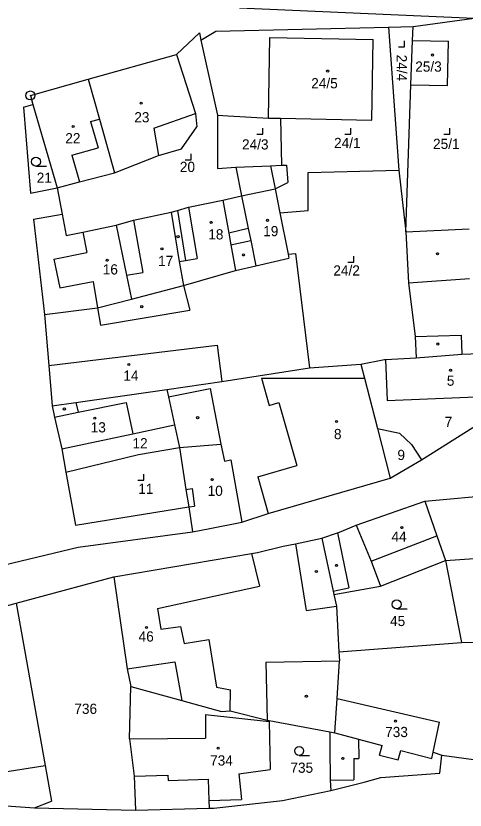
# Model space of a CAD drawing. Extents: x -779596 to -776743, y -1030330 to -1024513.
# Drawn here: x -778013.4 to -777938.4, y -1024989.8 to -1024857.5 of the extents above; entities that cross this region are included whole.
import ezdxf

# ---------------------------------------------------------------- set-up
doc = ezdxf.new("R2010")
doc.units = 0
for name, color, linetype in [('hranice parcel', 7, 'Continuous'), ('hranice vnitřní', 7, 'Continuous'), ('kultura', 7, 'Continuous'), ('Kód', 7, 'Continuous'), ('č_pacel stav_', 7, 'Continuous'), ('č_parcel poz_', 7, 'Continuous')]:
    doc.layers.add(name, color=color, linetype=linetype)

msp = doc.modelspace()

# ---------------------------------------------------------------- linework, layer by layer
at = {"layer": 'hranice parcel'}
for points in [[(-777976.03, -1024856.17), (-777936.91, -1024857.84)], [(-777947.1, -1024859.26), (-777936.91, -1024857.84)], [(-777986.58, -1024863.92), (-777982.75, -1024860.33)], [(-777982.75, -1024860.33), (-777982.49, -1024861.51)], [(-777982.49, -1024861.51), (-777979.99, -1024860.03)], [(-777979.99, -1024860.03), (-777951.2, -1024859.36)], [(-777951.2, -1024859.36), (-777947.1, -1024859.26)], [(-777951.2, -1024859.36), (-777949.5, -1024883.2)], [(-777947.18, -1024861.56), (-777947.1, -1024859.26)], [(-777982.49, -1024861.51), (-777979.73, -1024874.05)], [(-777971.23, -1024874.51), (-777970.97, -1024861.09)], [(-777970.97, -1024861.09), (-777953.73, -1024861.43)], [(-777953.99, -1024874.84), (-777953.73, -1024861.43)], [(-777947.45, -1024868.95), (-777947.18, -1024861.56)], [(-777947.18, -1024861.56), (-777941.2, -1024861.68)], [(-777941.34, -1024869.07), (-777941.2, -1024861.68)], [(-778001.29, -1024868.05), (-777986.58, -1024863.92)], [(-777986.58, -1024863.92), (-777983.39, -1024873.77)], [(-778010.93, -1024870.75), (-778001.29, -1024868.05)], [(-778001.29, -1024868.05), (-777999.41, -1024874.7)], [(-777948.32, -1024893.45), (-777947.45, -1024868.95)], [(-777947.45, -1024868.95), (-777941.34, -1024869.07)], [(-778010.93, -1024870.75), (-778010.5, -1024872.23)], [(-778012.1, -1024872.68), (-778010.5, -1024872.23)], [(-778010.5, -1024872.23), (-778006.46, -1024886.12)], [(-778012.1, -1024872.68), (-778010.91, -1024887.01)], [(-777999.41, -1024874.7), (-777996.89, -1024883.62)], [(-777983.39, -1024873.77), (-777983.17, -1024875.96)], [(-777979.73, -1024874.05), (-777977.93, -1024874.15)], [(-777979.73, -1024874.05), (-777979.72, -1024882.89)], [(-777977.93, -1024874.15), (-777971.23, -1024874.51)], [(-777971.23, -1024874.51), (-777969.23, -1024874.55)], [(-777969.23, -1024874.55), (-777969.04, -1024882.38)], [(-777969.23, -1024874.55), (-777953.99, -1024874.84)], [(-777985.73, -1024879.66), (-777983.17, -1024875.96)], [(-777989.57, -1024880.74), (-777985.73, -1024879.66)], [(-777996.89, -1024883.62), (-777989.57, -1024880.74)], [(-777979.72, -1024882.89), (-777976.68, -1024882.72)], [(-777976.68, -1024882.72), (-777970.86, -1024882.46)], [(-777976.68, -1024882.72), (-777975.72, -1024887.47)], [(-777970.86, -1024882.46), (-777969.04, -1024882.38)], [(-777969.04, -1024882.38), (-777968.24, -1024882.35)], [(-777968.24, -1024882.35), (-777968, -1024885.23)], [(-778002.75, -1024885.15), (-777996.89, -1024883.62)], [(-777964.6, -1024883.6), (-777949.5, -1024883.2)], [(-777964.6, -1024889.9), (-777964.6, -1024883.6)], [(-777949.5, -1024883.2), (-777948.32, -1024893.45)], [(-778006.46, -1024886.12), (-778002.75, -1024885.15)], [(-777970.1, -1024886.29), (-777968, -1024885.23)], [(-778010.91, -1024887.01), (-778006.46, -1024886.12)], [(-778006.46, -1024886.12), (-778005.64, -1024890.52)], [(-777970.1, -1024886.29), (-777969.3, -1024890.31)], [(-777984.56, -1024889.36), (-777978.84, -1024888.2)], [(-777978.84, -1024888.2), (-777975.72, -1024887.47)], [(-777978.84, -1024888.2), (-777977.83, -1024893.69)], [(-777986.4, -1024889.89), (-777984.56, -1024889.36)], [(-778010.4, -1024891.35), (-778005.64, -1024890.52)], [(-778005.64, -1024890.52), (-778004.97, -1024894.1)], [(-777993.71, -1024891.52), (-777987.44, -1024890.17)], [(-777987.44, -1024890.17), (-777986.4, -1024889.89)], [(-777987.44, -1024890.17), (-777986.13, -1024898.41)], [(-777969.3, -1024890.31), (-777964.6, -1024889.9)], [(-777969.3, -1024890.31), (-777967.93, -1024897.19)], [(-778010.4, -1024891.35), (-778008.58, -1024907.27)], [(-777996.65, -1024892.36), (-777993.71, -1024891.52)], [(-778004.97, -1024894.1), (-778002.18, -1024893.52)], [(-778002.18, -1024893.52), (-777996.65, -1024892.36)], [(-777996.65, -1024892.36), (-777994.91, -1024900.71)], [(-777948.32, -1024893.45), (-777937.75, -1024892.96)], [(-777948.32, -1024893.45), (-777947.88, -1024901.99)], [(-777977.83, -1024893.69), (-777977.48, -1024895.62)], [(-777977.48, -1024895.62), (-777976.7, -1024899.92)], [(-777967.93, -1024897.19), (-777966.73, -1024897.09)], [(-777967.93, -1024897.19), (-777967.8, -1024897.86)], [(-777966.73, -1024897.09), (-777964.35, -1024916.13)], [(-777986.13, -1024898.41), (-777985.4, -1024902.41)], [(-777973.3, -1024899.13), (-777967.8, -1024897.86)], [(-777985.4, -1024902.41), (-777976.7, -1024899.92)], [(-777976.7, -1024899.92), (-777973.3, -1024899.13)], [(-777994.91, -1024900.71), (-777994.08, -1024904.67)], [(-777994.08, -1024904.67), (-777985.4, -1024902.41)], [(-777947.88, -1024901.99), (-777946.73, -1024910.93)], [(-777999.74, -1024906.13), (-777994.08, -1024904.67)], [(-778008.58, -1024907.27), (-777999.74, -1024906.13)], [(-778008.58, -1024907.27), (-778007.87, -1024915.76)], [(-777946.73, -1024910.93), (-777946.58, -1024914.45)], [(-777951.86, -1024914.77), (-777951.7, -1024914.76)], [(-777951.7, -1024914.76), (-777946.58, -1024914.45)], [(-777951.7, -1024914.76), (-777951.42, -1024921.59)], [(-778007.87, -1024915.76), (-778007.31, -1024922.47)], [(-777964.35, -1024916.13), (-777955.82, -1024915.54)], [(-777955.82, -1024915.54), (-777951.86, -1024914.77)], [(-777955.82, -1024915.54), (-777955.22, -1024917.86)], [(-777979, -1024918.44), (-777964.35, -1024916.13)], [(-777988.18, -1024919.75), (-777979, -1024918.44)], [(-777955.22, -1024917.86), (-777953.06, -1024926.27)], [(-778003.35, -1024921.91), (-777988.18, -1024919.75)], [(-777988.18, -1024919.75), (-777987.91, -1024920.97)], [(-777987.91, -1024920.97), (-777986.89, -1024925.66)], [(-777951.42, -1024921.59), (-777931.23, -1024920.76)], [(-777945.67, -1024931.45), (-777928.59, -1024920.69)], [(-778007.31, -1024922.47), (-778003.35, -1024921.91)], [(-778007.31, -1024922.47), (-778006.88, -1024924.34)], [(-778006.88, -1024924.34), (-778005.69, -1024929.61)], [(-777993.83, -1024927.12), (-777986.89, -1024925.66)], [(-777986.89, -1024925.66), (-777986.08, -1024929.41)], [(-777953.06, -1024926.27), (-777950.94, -1024934.52)], [(-777953.06, -1024926.27), (-777949.39, -1024927.01)], [(-778005.69, -1024929.61), (-777993.83, -1024927.12)], [(-777949.39, -1024927.01), (-777947.35, -1024928.93)], [(-777986.08, -1024929.41), (-777979.14, -1024928.83)], [(-777979.14, -1024928.83), (-777978.58, -1024931.69)], [(-777947.35, -1024928.93), (-777945.67, -1024931.45)], [(-778005.69, -1024929.61), (-778005.03, -1024933.5)], [(-778005.03, -1024933.5), (-777992.92, -1024930.56)], [(-777992.92, -1024930.56), (-777986.08, -1024929.41)], [(-777986.08, -1024929.41), (-777984.99, -1024936.41)], [(-777978.58, -1024931.69), (-777977.51, -1024931.49)], [(-777977.51, -1024931.49), (-777975.66, -1024941.84)], [(-777950.94, -1024934.52), (-777945.67, -1024931.45)], [(-778005.03, -1024933.5), (-778003.43, -1024942.34)], [(-777971.26, -1024940.42), (-777950.94, -1024934.52)], [(-777984.99, -1024936.41), (-777984.53, -1024939.32)], [(-777945.13, -1024938.37), (-777932.96, -1024937.24)], [(-777956.59, -1024942.37), (-777945.13, -1024938.37)], [(-777945.13, -1024938.37), (-777943.13, -1024944.14)], [(-778003.43, -1024942.34), (-777984.53, -1024939.32)], [(-777984.53, -1024939.32), (-777983.88, -1024943.49)], [(-777975.66, -1024941.84), (-777971.26, -1024940.42)], [(-777980.98, -1024942.91), (-777975.66, -1024941.84)], [(-777959.36, -1024943.52), (-777956.59, -1024942.37)], [(-778002.98, -1024946.02), (-777983.88, -1024943.49)], [(-777983.88, -1024943.49), (-777980.98, -1024942.91)], [(-777962.34, -1024944.54), (-777959.68, -1024943.63)], [(-777959.68, -1024943.63), (-777959.36, -1024943.52)], [(-777966.7, -1024945.44), (-777962.34, -1024944.54)], [(-777962.34, -1024944.54), (-777960.42, -1024953.35)], [(-777943.13, -1024944.14), (-777941.71, -1024948.25)], [(-778018.06, -1024949.63), (-778002.98, -1024946.02)], [(-777973.07, -1024946.92), (-777968.75, -1024945.87)], [(-777968.75, -1024945.87), (-777966.7, -1024945.44)], [(-777997.02, -1024950.99), (-777974.06, -1024947.09)], [(-777974.06, -1024947.09), (-777973.07, -1024946.92)], [(-777952.52, -1024952.51), (-777941.71, -1024948.25)], [(-777941.71, -1024948.25), (-777939.01, -1024961.93)], [(-778013.31, -1024955.35), (-777997.02, -1024950.99)], [(-777997.02, -1024950.99), (-777994.8, -1024966.29)], [(-777960.3, -1024953.91), (-777952.52, -1024952.51)], [(-777960.42, -1024953.35), (-777960.3, -1024953.91)], [(-777960.3, -1024953.91), (-777959.88, -1024955.86)], [(-778022.98, -1024958.03), (-778013.31, -1024955.35)], [(-778013.31, -1024955.35), (-778008.47, -1024982.41)], [(-777959.88, -1024955.86), (-777959.47, -1024963.47)], [(-777959.47, -1024963.47), (-777939.01, -1024961.93)], [(-777939.01, -1024961.93), (-777928.89, -1024961.65)], [(-777959.47, -1024963.47), (-777959.37, -1024964.95)], [(-777959.77, -1024971.24), (-777959.37, -1024964.95)], [(-777994.8, -1024966.29), (-777994.17, -1024969.23)], [(-777994.39, -1024977.98), (-777994.17, -1024969.23)], [(-777994.17, -1024969.23), (-777985.66, -1024971.57)], [(-777985.66, -1024971.57), (-777979.03, -1024973.38)], [(-777960.14, -1024976.97), (-777959.77, -1024971.24)], [(-777959.77, -1024971.24), (-777942.72, -1024975.21)], [(-777979.03, -1024973.38), (-777977.59, -1024973.27)], [(-777977.59, -1024973.27), (-777971.41, -1024974.83)], [(-777971.41, -1024974.83), (-777971.11, -1024974.89)], [(-777971.11, -1024974.89), (-777961, -1024976.81)], [(-777971.11, -1024974.89), (-777971.1, -1024975.08)], [(-777971.1, -1024975.08), (-777970.91, -1024983.06)], [(-777943.75, -1024980.21), (-777942.72, -1024975.21)], [(-777961, -1024976.81), (-777960.98, -1024979.41)], [(-777961, -1024976.81), (-777960.14, -1024976.97)], [(-777994.39, -1024977.98), (-777993.62, -1024984.18)], [(-777960.98, -1024979.41), (-777960.93, -1024984.85)], [(-777943.75, -1024980.21), (-777942.33, -1024980.67)], [(-777942.63, -1024983.67), (-777942.33, -1024980.67)], [(-777942.33, -1024980.67), (-777925.63, -1024982.94)], [(-778008.47, -1024982.41), (-778007.41, -1024988.34)], [(-777976.18, -1024983.81), (-777970.91, -1024983.06)], [(-777993.62, -1024984.18), (-777993.41, -1024989.84)], [(-777976.18, -1024983.81), (-777975.73, -1024988.07)], [(-777960.93, -1024984.85), (-777960.81, -1024986.57)], [(-777955.25, -1024985.21), (-777952.48, -1024984.43)], [(-777952.48, -1024984.43), (-777942.63, -1024983.67)], [(-777960.81, -1024986.57), (-777955.25, -1024985.21)], [(-777968.89, -1024988.24), (-777960.81, -1024986.57)], [(-778027.49, -1024988.25), (-778010.26, -1024989.46)], [(-778010.26, -1024989.46), (-778007.41, -1024988.34)], [(-777981.17, -1024988.26), (-777975.73, -1024988.07)], [(-777981.17, -1024988.26), (-777981.12, -1024989.53)], [(-777980.35, -1024989.51), (-777968.89, -1024988.24)], [(-778010.26, -1024989.46), (-777993.41, -1024989.84)], [(-777993.41, -1024989.84), (-777981.12, -1024989.53)], [(-777981.12, -1024989.53), (-777980.35, -1024989.51)]]:
    msp.add_lwpolyline(points, dxfattribs=at)
at = {"layer": 'hranice vnitřní'}
for points in [[(-778000.91, -1024875.11), (-777999.41, -1024874.7)], [(-777990.33, -1024876.18), (-777983.39, -1024873.77)], [(-778000.91, -1024875.11), (-777999.65, -1024879.46)], [(-777990.33, -1024876.18), (-777989.57, -1024880.74)], [(-778004.04, -1024880.72), (-777999.65, -1024879.46)], [(-778004.04, -1024880.72), (-778002.75, -1024885.15)], [(-777970.86, -1024882.46), (-777970.1, -1024886.29)], [(-777975.72, -1024887.47), (-777970.1, -1024886.29)], [(-777975.72, -1024887.47), (-777974.59, -1024892.92)], [(-777984.56, -1024889.36), (-777983.09, -1024897.93)], [(-777986.4, -1024889.89), (-777985.07, -1024898.24)], [(-777993.71, -1024891.52), (-777992.18, -1024900.23)], [(-778002.18, -1024893.52), (-778001.51, -1024896.92)], [(-777974.59, -1024892.92), (-777977.83, -1024893.69)], [(-777974.59, -1024892.92), (-777974.17, -1024894.93)], [(-777977.48, -1024895.62), (-777974.17, -1024894.93)], [(-777974.17, -1024894.93), (-777973.3, -1024899.13)], [(-778007, -1024898), (-778001.51, -1024896.92)], [(-778007, -1024898), (-778006, -1024902.79)], [(-777986.13, -1024898.41), (-777985.07, -1024898.24)], [(-777985.07, -1024898.24), (-777983.09, -1024897.93)], [(-777994.91, -1024900.71), (-777992.18, -1024900.23)], [(-777947.88, -1024901.99), (-777937.7, -1024901.24)], [(-778006, -1024902.79), (-778000.48, -1024901.76)], [(-778000.48, -1024901.76), (-777999.74, -1024906.13)], [(-777985.4, -1024902.41), (-777984.31, -1024906.54)], [(-777999.74, -1024906.13), (-777999.25, -1024909.02)], [(-777999.25, -1024909.02), (-777984.31, -1024906.54)], [(-777946.73, -1024910.93), (-777939.09, -1024910.67)], [(-777939.09, -1024910.67), (-777938.96, -1024913.88)], [(-778007.87, -1024915.76), (-777979.79, -1024912.37)], [(-777979.79, -1024912.37), (-777979, -1024918.44)], [(-777946.58, -1024914.45), (-777938.96, -1024913.88)], [(-777938.96, -1024913.88), (-777931.52, -1024913.58)], [(-777972.38, -1024917.88), (-777955.22, -1024917.86)], [(-777972.38, -1024917.88), (-777971.08, -1024922.39)], [(-777987.91, -1024920.97), (-777980.97, -1024919.59)], [(-777980.97, -1024919.59), (-777979.14, -1024928.83)], [(-778003.35, -1024921.91), (-778002.96, -1024923.55)], [(-778002.96, -1024923.55), (-777994.93, -1024921.93)], [(-777994.93, -1024921.93), (-777993.83, -1024927.12)], [(-777971.08, -1024922.39), (-777969.5, -1024921.94)], [(-777969.5, -1024921.94), (-777966.48, -1024932.41)], [(-778006.88, -1024924.34), (-778002.96, -1024923.55)], [(-777973.01, -1024934.31), (-777966.48, -1024932.41)], [(-777973.01, -1024934.31), (-777971.26, -1024940.42)], [(-777984.99, -1024936.41), (-777983.93, -1024936.24)], [(-777983.93, -1024936.24), (-777983.57, -1024939.17)], [(-777984.53, -1024939.32), (-777983.57, -1024939.17)], [(-777956.59, -1024942.37), (-777954.11, -1024948.38)], [(-777959.68, -1024943.63), (-777957.79, -1024952.78)], [(-777954.11, -1024948.38), (-777943.13, -1024944.14)], [(-777966.7, -1024945.44), (-777964.93, -1024956.57)], [(-777974.06, -1024947.09), (-777972.71, -1024952.52)], [(-777941.71, -1024948.25), (-777932.15, -1024947.55)], [(-777954.11, -1024948.38), (-777952.52, -1024952.51)], [(-777989.75, -1024956.23), (-777972.71, -1024952.52)], [(-777960.42, -1024953.35), (-777957.79, -1024952.78)], [(-777989.75, -1024956.23), (-777989.15, -1024959.69)], [(-777964.93, -1024956.57), (-777959.88, -1024955.86)], [(-777989.15, -1024959.69), (-777985.92, -1024959.25)], [(-777985.92, -1024959.25), (-777985.3, -1024962.05)], [(-777985.3, -1024962.05), (-777981.19, -1024961.4)], [(-777981.19, -1024961.4), (-777979.89, -1024969.35)], [(-777971.67, -1024965.2), (-777959.37, -1024964.95)], [(-777994.8, -1024966.29), (-777986.84, -1024965.14)], [(-777986.84, -1024965.14), (-777985.66, -1024971.57)], [(-777971.67, -1024965.2), (-777971.41, -1024974.83)], [(-777979.89, -1024969.35), (-777977.55, -1024969.77)], [(-777977.59, -1024973.27), (-777977.55, -1024969.77)], [(-777981.74, -1024973.89), (-777971.1, -1024975.08)], [(-777981.74, -1024973.89), (-777981.72, -1024977.86)], [(-777960.14, -1024976.97), (-777956.19, -1024978.02)], [(-777994.39, -1024977.98), (-777981.72, -1024977.86)], [(-777956.19, -1024978.02), (-777952.27, -1024979.05)], [(-777956.19, -1024978.02), (-777956.17, -1024981.22)], [(-777952.7, -1024980.66), (-777952.27, -1024979.05)], [(-777952.7, -1024980.66), (-777949.57, -1024981.47)], [(-777949.57, -1024981.47), (-777949.15, -1024979.88)], [(-777949.15, -1024979.88), (-777943.97, -1024981.25)], [(-777943.97, -1024981.25), (-777943.75, -1024980.21)], [(-777956.99, -1024981.22), (-777956.97, -1024984.79)], [(-777956.99, -1024981.22), (-777956.17, -1024981.22)], [(-778027.27, -1024985.36), (-778008.47, -1024982.41)], [(-777993.62, -1024984.18), (-777988.01, -1024983.99)], [(-777988.01, -1024983.99), (-777987.96, -1024984.92)], [(-777987.96, -1024984.92), (-777981.3, -1024984.7)], [(-777981.3, -1024984.7), (-777981.17, -1024988.26)], [(-777960.93, -1024984.85), (-777956.97, -1024984.79)]]:
    msp.add_lwpolyline(points, dxfattribs=at)
at = {"layer": 'kultura'}
for points in [[(-777949.54, -1024862.65), (-777948.54, -1024862.65), (-777948.54, -1024861.65)], [(-777973.17, -1024877.18), (-777972.17, -1024877.18), (-777972.17, -1024876.18)], [(-777958.51, -1024877.18), (-777957.51, -1024877.18), (-777957.51, -1024876.18)], [(-777941.95, -1024877.18), (-777940.95, -1024877.18), (-777940.95, -1024876.18)], [(-777985.11, -1024881.45), (-777984.11, -1024881.45), (-777984.11, -1024880.45)], [(-778010.01, -1024882.54), (-778008.26, -1024882.54)], [(-777958, -1024898.55), (-777957, -1024898.55), (-777957, -1024897.55)], [(-777993, -1024934.85), (-777992, -1024934.85), (-777992, -1024933.85)], [(-777949.84, -1024956.31), (-777948.09, -1024956.31)], [(-777966.1, -1024980.72), (-777964.35, -1024980.72)]]:
    msp.add_lwpolyline(points, dxfattribs=at)
for centre, radius in [((-777943.85, -1024864.01), 0.175), ((-777961.34, -1024866.68), 0.175), ((-777992.44, -1024872.02), 0.175), ((-778003.79, -1024875.91), 0.175), ((-778010.01, -1024881.79), 0.75), ((-777980.78, -1024891.9), 0.175), ((-777971.38, -1024891.55), 0.175), ((-777986.31, -1024894.27), 0.175), ((-777988.99, -1024896.29), 0.175), ((-777975.37, -1024897.32), 0.175), ((-777943.03, -1024897.12), 0.175), ((-777998.12, -1024898.21), 0.175), ((-777992.36, -1024905.94), 0.175), ((-777942.97, -1024912.17), 0.175), ((-777994.51, -1024915.58), 0.175), ((-777940.84, -1024916.54), 0.175), ((-778005.26, -1024922.99), 0.175), ((-778000.17, -1024924.51), 0.175), ((-777983.03, -1024924.44), 0.175), ((-777959.87, -1024925.07), 0.175), ((-777980.62, -1024934.76), 0.175), ((-777948.99, -1024942.76), 0.175), ((-777959.87, -1024949.06), 0.175), ((-777963.23, -1024950.08), 0.175), ((-777949.84, -1024955.56), 0.75), ((-777991.57, -1024959.4), 0.175), ((-777964.9, -1024970.87), 0.175), ((-777950.02, -1024975), 0.175), ((-777979.6, -1024979.51), 0.175), ((-777966.1, -1024979.97), 0.75), ((-777958.83, -1024981.22), 0.175)]:
    msp.add_circle(centre, radius, dxfattribs=at)
at = {"layer": 'Kód'}
for radius in [0.75, 0.032]:
    msp.add_circle((-778010.93, -1024870.75), radius, dxfattribs=at)

# ---------------------------------------------------------------- texts
at = {"layer": 'č_pacel stav_'}
msp.add_text('24/4', height=1.7, rotation=270.00215, dxfattribs=at).set_placement((-777949.841, -1024863.94))
for s, p in [('25/3', (-777946.74, -1024866.78)), ('24/5', (-777964.09, -1024869.56)), ('23', (-777993.6, -1024875.23)), ('22', (-778005.11, -1024878.72)), ('24/3', (-777975.63, -1024879.75)), ('24/1', (-777960.28, -1024879.51)), ('25/1', (-777943.77, -1024879.66)), ('20', (-777986, -1024883.5)), ('18', (-777981.26, -1024894.74)), ('19', (-777972.1, -1024894.2)), ('17', (-777989.63, -1024899.16)), ('16', (-777998.86, -1024900.58)), ('24/2', (-777960.4, -1024900.76)), ('14', (-777995.43, -1024918.28)), ('5', (-777941.47, -1024919.12)), ('13', (-778000.87, -1024926.9)), ('8', (-777960.3, -1024928.02)), ('11', (-777992.94, -1024937.15)), ('10', (-777981.37, -1024937.48)), ('44', (-777950.71, -1024945.12)), ('46', (-777992.88, -1024961.75)), ('733', (-777951.76, -1024977.67)), ('734', (-777980.95, -1024982.41))]:
    msp.add_text(s, height=1.7, dxfattribs=at).set_placement(p)
at = {"layer": 'č_parcel poz_'}
for s, p in [('21', (-778009.87, -1024885.3)), ('7', (-777941.83, -1024926)), ('12', (-777993.9, -1024929.55)), ('9', (-777949.71, -1024931.5)), ('45', (-777950.94, -1024959.17)), ('736', (-778003.6, -1024973.8)), ('735', (-777967.56, -1024983.62))]:
    msp.add_text(s, height=1.7, dxfattribs=at).set_placement(p)

doc.saveas('drawing.dxf')
